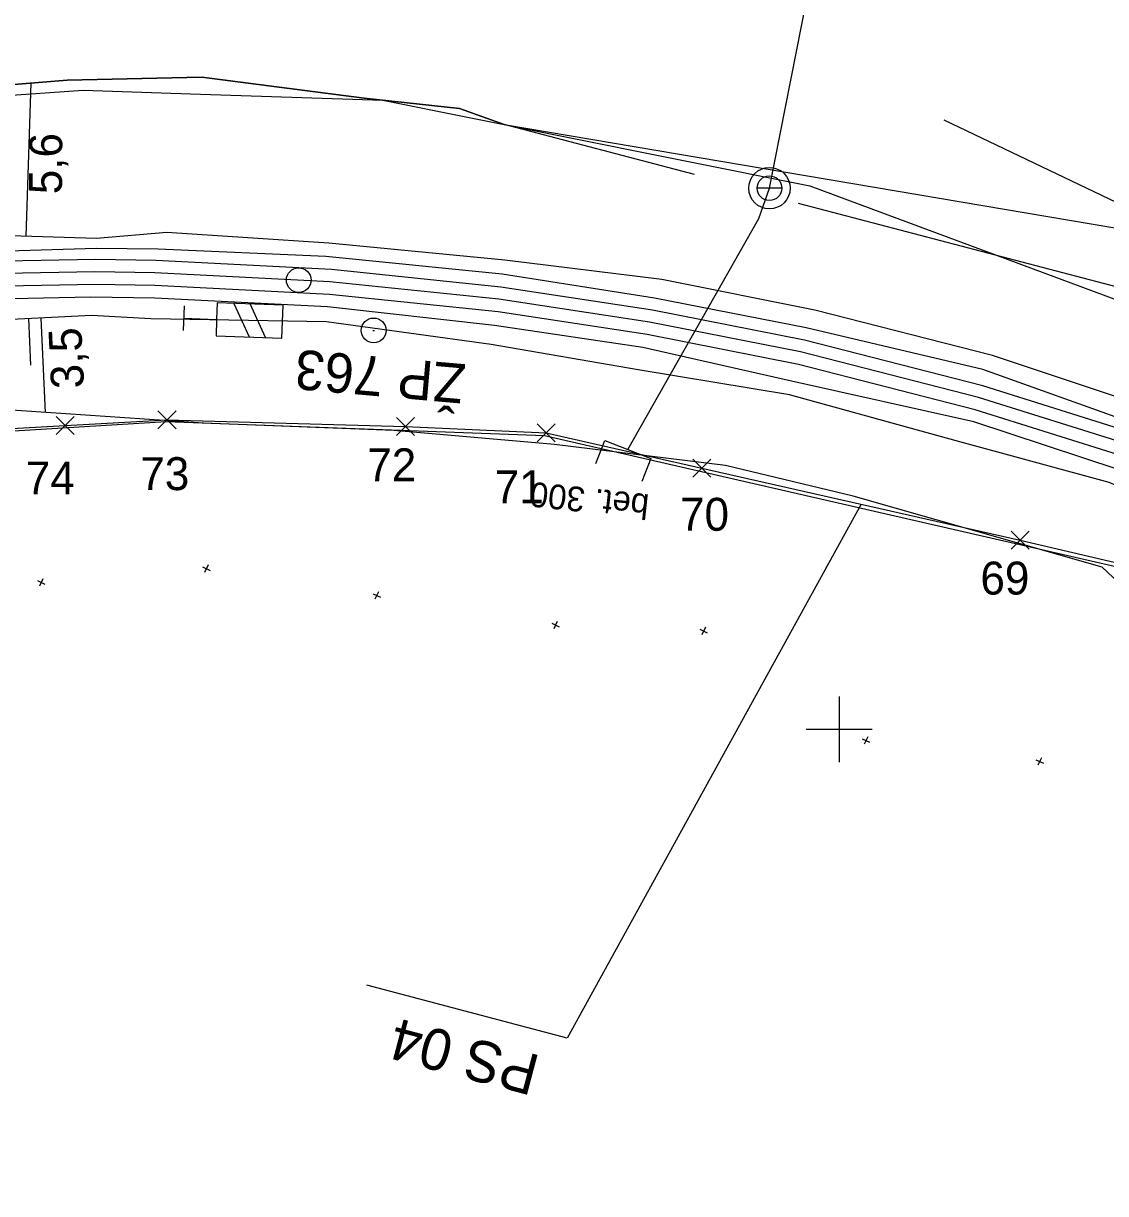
# Model space of a CAD drawing. Extents: x -805011 to -803920, y -1150790 to -1150234.
# Drawn here: x -804349.5 to -804283.8, y -1150528.2 to -1150457.1 of the extents above; entities that cross this region are included whole.
import ezdxf

# ---------------------------------------------------------------- set-up
doc = ezdxf.new("R2010")
doc.units = 0
for name, color, linetype in [('0381KM032-037P - Vrstva 1', 7, 'Continuous'), ('0381KM032-037P - Vrstva 17', 7, 'Continuous'), ('0381KM032-037P - Vrstva 19', 7, 'Continuous'), ('0381KM032-037P - Vrstva 4', 7, 'Continuous'), ('0381KM032-037P - Vrstva 41', 7, 'Continuous'), ('0381KM032-037P - Vrstva 43', 7, 'Continuous'), ('0381KM032-037P - Vrstva 48', 7, 'Continuous'), ('0381KM032-037P - Vrstva 49', 7, 'Continuous'), ('0381KM032-037P - Vrstva 51', 7, 'Continuous'), ('0381KM032-037P - Vrstva 7', 7, 'Continuous'), ('Default', 7, 'Continuous'), ('hran DP - hran DP', 7, 'Continuous'), ('krizky_1000 - Vrstva 1', 7, 'Continuous'), ('PSR_C2_2_Lomove_body_Vimperk - Vrstva 60', 7, 'Continuous'), ('PSR_C2_2_trasa_Vimperk - Kabelová trasa', 7, 'Continuous'), ('SOPS', 7, 'Continuous'), ('vyt_sit - stávající', 7, 'Continuous')]:
    doc.layers.add(name, color=color, linetype=linetype)

msp = doc.modelspace()

# ---------------------------------------------------------------- linework, layer by layer
at = {"layer": '0381KM032-037P - Vrstva 1'}
for points in [[(-804345.19, -1150472.22), (-804355.1, -1150472.39), (-804364.37, -1150472.93), (-804373.68, -1150473.77), (-804382.25, -1150474.73), (-804390.38, -1150475.71), (-804394.38, -1150476.22)], [(-804222.979, -1150515.095), (-804226.42, -1150512.48), (-804234.26, -1150506.83), (-804242.54, -1150501.49), (-804250.96, -1150496.61), (-804260.8, -1150491.55), (-804271.59, -1150486.76), (-804282.48, -1150482.69), (-804291.53, -1150479.85), (-804302.34, -1150477.08), (-804311.51, -1150475.27), (-804320.67, -1150473.88), (-804330.92, -1150472.81), (-804341.55, -1150472.27), (-804345.19, -1150472.22)]]:
    msp.add_lwpolyline(points, dxfattribs=at)
at = {"layer": '0381KM032-037P - Vrstva 17'}
msp.add_line((-804323.06, -1150462.29), (-804328.85, -1150461.67), dxfattribs=at)
for points in [[(-804328.85, -1150461.67), (-804338.71, -1150460.38), (-804346.87, -1150460.56), (-804368.54, -1150462.33)], [(-804308.78, -1150466.29), (-804320.34, -1150463.27), (-804323.06, -1150462.29)], [(-804223.8, -1150504.14), (-804238.39, -1150493.96), (-804260.56, -1150483.05), (-804280.24, -1150473.89), (-804302.47, -1150468.07)]]:
    msp.add_lwpolyline(points, dxfattribs=at)
at = {"layer": '0381KM032-037P - Vrstva 19'}
msp.add_line((-804304.23, -1150467.13), (-804292.588, -1150408.116), dxfattribs=at)
msp.add_lwpolyline([(-804312.83, -1150483), (-804304.87, -1150468.97), (-804304.23, -1150467.13)], dxfattribs=at)
at = {"layer": '0381KM032-037P - Vrstva 4'}
for points in [[(-804225.7, -1150511.47), (-804233.93, -1150505.38), (-804241.84, -1150500.35), (-804251.18, -1150495.03), (-804260.27, -1150490.25), (-804271.39, -1150485.02), (-804282.1, -1150481.42), (-804291.28, -1150478.15), (-804302, -1150475.62), (-804311.22, -1150473.82), (-804320.47, -1150472.35), (-804331.17, -1150471.28), (-804341.36, -1150470.84), (-804345.11, -1150470.79), (-804355.15, -1150471.09), (-804364.49, -1150471.64), (-804373.72, -1150472.46), (-804382.56, -1150473.46), (-804390.64, -1150474.3), (-804394.58, -1150474.82), (-804430.68, -1150479.4), (-804471.16, -1150484.87), (-804515.79, -1150490.21)], [(-804222.47, -1150514.31), (-804225.93, -1150511.88), (-804233.81, -1150506.22), (-804242.12, -1150500.85), (-804250.57, -1150495.96), (-804260.44, -1150490.89), (-804271.28, -1150486.07), (-804282.21, -1150481.99), (-804291.28, -1150479.14), (-804302.11, -1150476.36), (-804311.33, -1150474.54), (-804320.55, -1150473.14), (-804330.83, -1150472.06), (-804341.5, -1150471.52), (-804345.16, -1150471.47), (-804355.1, -1150471.64), (-804364.39, -1150472.17), (-804373.73, -1150473.02), (-804382.33, -1150473.97), (-804390.45, -1150474.97), (-804394.45, -1150475.48), (-804430.79, -1150480.07), (-804470.48, -1150485.06), (-804515.61, -1150490.8)], [(-804223.37, -1150515.97), (-804226.85, -1150513.1), (-804234.67, -1150507.48), (-804242.93, -1150502.16), (-804251.31, -1150497.29), (-804261.13, -1150492.25), (-804271.85, -1150487.49), (-804282.71, -1150483.42), (-804291.73, -1150480.59), (-804302.46, -1150477.85), (-804311.66, -1150476.01), (-804320.71, -1150474.65), (-804330.94, -1150473.58), (-804341.55, -1150473.05), (-804345.16, -1150472.99), (-804355.02, -1150473.16), (-804364.28, -1150473.69), (-804373.57, -1150474.51), (-804382.12, -1150475.46), (-804390.26, -1150476.46), (-804394.25, -1150476.96), (-804430.61, -1150481.56), (-804470.33, -1150486.56), (-804515.43, -1150492.3)], [(-804235.83, -1150507.71), (-804243.11, -1150502.63), (-804252.43, -1150497.68), (-804261.4, -1150493.06), (-804272.11, -1150488.47), (-804283.06, -1150484.22), (-804291.82, -1150481.32), (-804302.89, -1150478.85), (-804311.92, -1150476.81), (-804320.92, -1150475.47), (-804331.06, -1150474.34), (-804341.56, -1150473.81), (-804345.45, -1150473.75), (-804355.04, -1150473.96), (-804364.32, -1150474.45), (-804373.64, -1150475.34), (-804382.1, -1150476.35), (-804390.24, -1150477.29), (-804394.24, -1150477.85), (-804430.45, -1150482.3), (-804470.19, -1150487.36), (-804515.37, -1150493.06)]]:
    msp.add_lwpolyline(points, dxfattribs=at)
at = {"layer": '0381KM032-037P - Vrstva 41'}
msp.add_line((-804303.48, -1150467.13), (-804304.98, -1150467.13), dxfattribs=at)
for radius in [1.259, 0.75]:
    msp.add_circle((-804304.23, -1150467.13), radius, dxfattribs=at)
at = {"layer": '0381KM032-037P - Vrstva 43'}
msp.add_lwpolyline([(-804314.771, -1150483.856), (-804314.229, -1150482.458), (-804311.431, -1150483.542), (-804311.974, -1150484.941)], dxfattribs=at)
at = {"layer": '0381KM032-037P - Vrstva 48'}
for p, q in [((-804349.36, -1150470.06), (-804349.076, -1150460.74)), ((-804349.234, -1150475.055), (-804349.098, -1150477.877)), ((-804348.485, -1150475.019), (-804348.208, -1150480.751))]:
    msp.add_line(p, q, dxfattribs=at)
at = {"layer": '0381KM032-037P - Vrstva 49'}
for p, q in [((-804338.322, -1150490.014), (-804338.538, -1150490.466)), ((-804338.656, -1150490.132), (-804338.204, -1150490.348)), ((-804348.686, -1150490.972), (-804348.234, -1150491.188)), ((-804348.352, -1150490.854), (-804348.568, -1150491.306)), ((-804328.306, -1150491.762), (-804327.854, -1150491.978)), ((-804327.972, -1150491.644), (-804328.188, -1150492.096)), ((-804317.446, -1150493.562), (-804316.994, -1150493.778)), ((-804317.112, -1150493.444), (-804317.328, -1150493.896)), ((-804308.456, -1150493.922), (-804308.004, -1150494.138)), ((-804308.122, -1150493.804), (-804308.338, -1150494.256)), ((-804298.596, -1150500.572), (-804298.144, -1150500.788)), ((-804298.262, -1150500.454), (-804298.478, -1150500.906)), ((-804288.046, -1150501.852), (-804287.594, -1150502.068)), ((-804287.712, -1150501.734), (-804287.928, -1150502.186))]:
    msp.add_line(p, q, dxfattribs=at)
for points in [[(-804541.806, -1150485.209), (-804536.325, -1150485.985), (-804530.599, -1150485.024), (-804524.609, -1150484.281), (-804503.761, -1150480.939), (-804473.972, -1150476.004), (-804446.961, -1150472.017), (-804437.24, -1150471.077), (-804431.751, -1150470.099), (-804429.717, -1150469.727), (-804427.076, -1150469.249), (-804388.45, -1150464.13), (-804374.42, -1150462.03), (-804368.54, -1150462.33), (-804346.87, -1150460.56), (-804338.71, -1150460.38), (-804328.85, -1150461.67), (-804323.06, -1150462.29), (-804320.34, -1150463.27)], [(-804328.85, -1150461.67), (-804323.06, -1150462.29), (-804320.34, -1150463.27)], [(-804320.34, -1150463.27), (-804278.12, -1150470.41)], [(-804221.1, -1150510.47), (-804225.19, -1150510.8), (-804233.52, -1150504.69), (-804241.09, -1150499.46), (-804250.66, -1150494.51), (-804260.04, -1150488.87), (-804271.07, -1150483.89), (-804281.58, -1150480.34), (-804290.68, -1150477.29), (-804301.47, -1150474.53), (-804310.76, -1150472.67), (-804320.3, -1150471.51), (-804330.99, -1150470.46), (-804340.83, -1150469.83), (-804345.1, -1150470.19), (-804354.95, -1150469.89)], [(-804226.97, -1150514.32), (-804233.94, -1150510.78), (-804236.52, -1150508.57), (-804243.93, -1150503.82), (-804252.72, -1150498.82), (-804262.25, -1150494.6), (-804273.33, -1150489.4), (-804283.59, -1150485.01), (-804292.89, -1150482.47), (-804303.02, -1150479.68), (-804312.2, -1150478.16), (-804321.12, -1150476.62), (-804331.14, -1150475.24), (-804341.8, -1150475.06), (-804345.41, -1150474.87), (-804355.14, -1150475.34), (-804364.22, -1150475.73), (-804373.58, -1150476.33), (-804382.14, -1150477.38), (-804390.01, -1150478.23), (-804394.36, -1150478.78), (-804430.35, -1150482.91), (-804470.16, -1150488.05), (-804515.21, -1150493.93)], [(-804276.15, -1150497.56), (-804284.03, -1150490.16), (-804299.15, -1150485.83), (-804306.89, -1150483.98), (-804317.28, -1150482.7), (-804327.05, -1150481.84), (-804338.6, -1150481.41), (-804350.55, -1150480.59), (-804360.54, -1150481.11), (-804374.96, -1150483.29), (-804385.39, -1150485.41), (-804391.71, -1150485.5), (-804430.73, -1150489.32), (-804470.3, -1150492.85), (-804514.17, -1150497.56)]]:
    msp.add_lwpolyline(points, dxfattribs=at)
at = {"layer": '0381KM032-037P - Vrstva 51'}
msp.add_lwpolyline([(-804222.47, -1150514.31), (-804222.23, -1150513.73), (-804221.1, -1150510.47), (-804220.62, -1150508.07), (-804220.01, -1150502.88), (-804222.18, -1150500.57), (-804227.38, -1150496.55), (-804235.69, -1150490.06), (-804246.55, -1150486.97), (-804255.48, -1150481.87), (-804266.7, -1150476.32), (-804278.12, -1150470.41), (-804293.62, -1150463)], dxfattribs=at)
at = {"layer": '0381KM032-037P - Vrstva 7'}
for p, q in [((-804339.775, -1150474.28), (-804339.825, -1150475.78)), ((-804336.768, -1150474.132), (-804335.836, -1150476.164)), ((-804334.837, -1150476.198), (-804335.769, -1150474.165))]:
    msp.add_line(p, q, dxfattribs=at)
msp.add_lwpolyline([(-804339.8, -1150475.03), (-804337.801, -1150475.097), (-804337.835, -1150476.097), (-804333.837, -1150476.232), (-804333.77, -1150474.233), (-804337.767, -1150474.098), (-804337.801, -1150475.097)], dxfattribs=at)
msp.add_circle((-804332.815, -1150472.714), 0.75, dxfattribs=at)
at = {"layer": 'hran DP - hran DP'}
for p, q in [((-804374.01, -1150463.14), (-804345.91, -1150461.18)), ((-804345.91, -1150461.18), (-804339.38, -1150461.4)), ((-804339.38, -1150461.4), (-804327.71, -1150461.78)), ((-804327.71, -1150461.78), (-804317.22, -1150463.88)), ((-804317.22, -1150463.88), (-804301.77, -1150466.98)), ((-804301.77, -1150466.98), (-804268.19, -1150479.5)), ((-804340.86, -1150481.33), (-804372.75, -1150483.24)), ((-804317.89, -1150482.17), (-804340.86, -1150481.33)), ((-804276.4, -1150491.69), (-804317.89, -1150482.17))]:
    msp.add_line(p, q, dxfattribs=at)
at = {"layer": 'krizky_1000 - Vrstva 1'}
for points in [[(-804300, -1150498), (-804300, -1150502)], [(-804302, -1150500), (-804298, -1150500)]]:
    msp.add_lwpolyline(points, dxfattribs=at)
at = {"layer": 'PSR_C2_2_Lomove_body_Vimperk - Vrstva 60'}
for p, q in [((-804341.368, -1150481.747), (-804340.268, -1150480.647)), ((-804340.268, -1150481.747), (-804341.368, -1150480.647)), ((-804347.557, -1150482.092), (-804346.457, -1150480.992)), ((-804346.457, -1150482.092), (-804347.557, -1150480.992)), ((-804326.877, -1150482.152), (-804325.777, -1150481.052)), ((-804325.777, -1150482.152), (-804326.877, -1150481.052)), ((-804318.341, -1150482.546), (-804317.241, -1150481.446)), ((-804317.241, -1150482.546), (-804318.341, -1150481.446)), ((-804308.884, -1150484.687), (-804307.784, -1150483.587)), ((-804307.784, -1150484.687), (-804308.884, -1150483.587)), ((-804289.552, -1150489.064), (-804288.452, -1150487.964)), ((-804288.452, -1150489.064), (-804289.552, -1150487.964))]:
    msp.add_line(p, q, dxfattribs=at)
at = {"layer": 'PSR_C2_2_trasa_Vimperk - Kabelová trasa'}
for points in [[(-804529.079, -1150496.274), (-804528.298, -1150496.202), (-804516.012, -1150498.692), (-804469.464, -1150493.331), (-804431.096, -1150489.424), (-804404.838, -1150486.852), (-804374.836, -1150483.323), (-804363.676, -1150482.47), (-804347.007, -1150481.542), (-804340.818, -1150481.197), (-804326.327, -1150481.602), (-804317.791, -1150481.996), (-804308.334, -1150484.137), (-804289.002, -1150488.514)], [(-804289.002, -1150488.514), (-804276.211, -1150491.505), (-804253.891, -1150501.391), (-804247.386, -1150504.47), (-804224.587, -1150517.682), (-804219.242, -1150521.518), (-804211.944, -1150528.206)]]:
    msp.add_lwpolyline(points, dxfattribs=at)
at = {"layer": 'SOPS'}
msp.add_lwpolyline([(-804298.668, -1150486.325), (-804316.509, -1150518.757), (-804328.678, -1150515.537)], dxfattribs=at)
at = {"layer": 'vyt_sit - stávající'}
msp.add_line((-804328.316, -1150475.773), (-804328.216, -1150475.773), dxfattribs=at)
msp.add_circle((-804328.266, -1150475.773), 0.756, dxfattribs=at)

# ---------------------------------------------------------------- texts
at = {"layer": '0381KM032-037P - Vrstva 43'}
msp.add_text('bet. 300', height=1.5, rotation=173.80264, dxfattribs=at).set_placement((-804311.481, -1150485.744))
at = {"layer": '0381KM032-037P - Vrstva 48'}
for s, rotation, p in [('5,6', 89.66954, (-804347.198, -1150467.502)), ('3,5', 92.76548, (-804345.847, -1150479.262))]:
    msp.add_text(s, height=2, rotation=rotation, dxfattribs=at).set_placement(p)
at = {"layer": 'Default'}
for s, p in [('72', (-804328.655, -1150484.934)), ('73', (-804342.439, -1150485.472)), ('74', (-804349.394, -1150485.737)), ('71', (-804320.914, -1150486.271)), ('70', (-804309.66, -1150487.94)), ('69', (-804291.418, -1150491.816))]:
    msp.add_text(s, height=2, dxfattribs=at).set_placement(p)
at = {"layer": 'SOPS'}
msp.add_text('PS 04', height=2.5, rotation=165.17834, dxfattribs=at).set_placement((-804318.051, -1150519.853))
at = {"layer": 'vyt_sit - stávající'}
msp.add_text('ŽP 763', height=2.4, rotation=175, dxfattribs=at).set_placement((-804322.606, -1150477.832))

doc.saveas('drawing.dxf')
